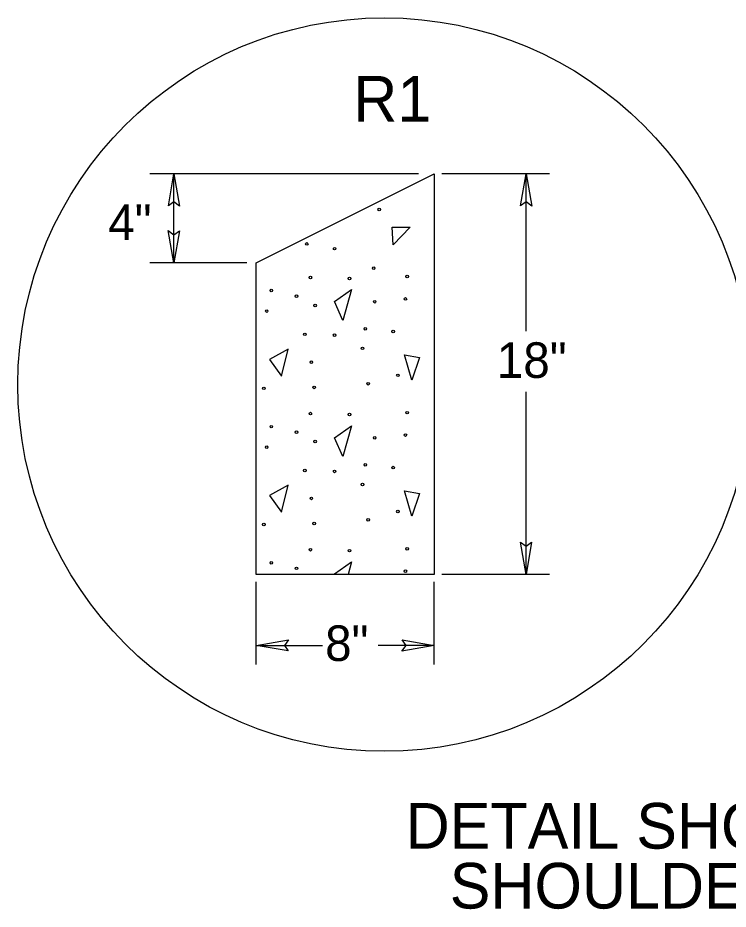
# Model space of a CAD drawing. Extents: x 1542177 to 1542464, y 45134 to 45344.
# Drawn here: x 1542311.98 to 1542327.96, y 45285.53 to 45305.56 of the extents above; entities that cross this region are included whole.
import ezdxf

# ---------------------------------------------------------------- set-up
doc = ezdxf.new("R2010")
doc.units = 0
for name, color, linetype in [('Default', 7, 'Continuous'), ('Typical Curb CELL', 7, 'Continuous'), ('Typical ID Circle CELL', 7, 'Continuous')]:
    doc.layers.add(name, color=color, linetype=linetype)

msp = doc.modelspace()

# ---------------------------------------------------------------- linework, layer by layer
at = {"layer": 'Default'}
for p, q in [((1542320.995, 45302.053), (1542314.954, 45302.053)), ((1542315.495, 45300.053), (1542315.495, 45302.053)), ((1542323.939, 45302.053), (1542321.515, 45302.053)), ((1542323.412, 45298.52), (1542323.412, 45302.053)), ((1542317.135, 45300.053), (1542314.954, 45300.053)), ((1542323.412, 45293.053), (1542323.412, 45297.151)), ((1542323.939, 45293.053), (1542321.515, 45293.053)), ((1542317.345, 45291.024), (1542317.345, 45292.884)), ((1542321.345, 45291.024), (1542321.345, 45292.884)), ((1542317.345, 45291.456), (1542318.834, 45291.456)), ((1542321.345, 45291.456), (1542320.085, 45291.456))]:
    msp.add_line(p, q, dxfattribs=at)
for points in [[(1542315.371, 45301.333), (1542315.495, 45302.053), (1542315.623, 45301.329), (1542315.495, 45301.421)], [(1542323.288, 45301.333), (1542323.412, 45302.053), (1542323.54, 45301.329), (1542323.412, 45301.421)], [(1542315.619, 45300.773), (1542315.495, 45300.053), (1542315.367, 45300.777), (1542315.495, 45300.685)], [(1542323.536, 45293.773), (1542323.412, 45293.053), (1542323.284, 45293.777), (1542323.412, 45293.685)], [(1542318.065, 45291.332), (1542317.345, 45291.456), (1542318.069, 45291.584), (1542317.977, 45291.456)], [(1542320.625, 45291.58), (1542321.345, 45291.456), (1542320.621, 45291.328), (1542320.713, 45291.456)]]:
    msp.add_lwpolyline(points, close=True, dxfattribs=at)
at = {"layer": 'Typical Curb CELL'}
for p, q in [((1542317.345, 45300.053), (1542321.345, 45302.053)), ((1542321.345, 45302.053), (1542321.345, 45293.053)), ((1542320.404, 45300.854), (1542320.803, 45300.854)), ((1542320.427, 45300.455), (1542320.404, 45300.854)), ((1542320.803, 45300.854), (1542320.427, 45300.455)), ((1542317.345, 45293.053), (1542317.345, 45300.053)), ((1542319.107, 45299.181), (1542319.487, 45299.451)), ((1542319.487, 45299.451), (1542319.295, 45298.759)), ((1542319.295, 45298.759), (1542319.107, 45299.181)), ((1542318.061, 45298.112), (1542317.644, 45297.883)), ((1542317.914, 45297.507), (1542318.061, 45298.112)), ((1542320.679, 45297.988), (1542321.014, 45297.924)), ((1542320.844, 45297.42), (1542320.679, 45297.988)), ((1542321.014, 45297.924), (1542320.844, 45297.42)), ((1542317.644, 45297.883), (1542317.914, 45297.507)), ((1542319.107, 45296.122), (1542319.487, 45296.392)), ((1542319.487, 45296.392), (1542319.295, 45295.7)), ((1542319.295, 45295.7), (1542319.107, 45296.122)), ((1542318.061, 45295.054), (1542317.644, 45294.824)), ((1542317.914, 45294.448), (1542318.061, 45295.054)), ((1542320.679, 45294.93), (1542321.014, 45294.866)), ((1542320.844, 45294.361), (1542320.679, 45294.93)), ((1542317.644, 45294.824), (1542317.914, 45294.448)), ((1542321.014, 45294.866), (1542320.844, 45294.361)), ((1542319.107, 45293.063), (1542319.487, 45293.334)), ((1542319.487, 45293.334), (1542319.409, 45293.053)), ((1542321.345, 45293.053), (1542317.345, 45293.053)), ((1542319.111, 45293.053), (1542319.107, 45293.063))]:
    msp.add_line(p, q, dxfattribs=at)
for centre in [(1542320.112, 45301.251), (1542318.48, 45300.477), (1542319.107, 45300.372), (1542319.986, 45299.933), (1542318.563, 45299.724), (1542319.443, 45299.703), (1542320.74, 45299.745), (1542317.684, 45299.43), (1542318.249, 45299.305), (1542318.668, 45299.096), (1542320.008, 45299.179), (1542320.699, 45299.242), (1542317.58, 45298.97), (1542319.798, 45298.572), (1542320.426, 45298.51), (1542318.438, 45298.447), (1542319.107, 45298.426), (1542319.736, 45298.132), (1542318.584, 45297.819), (1542320.531, 45297.525), (1542319.861, 45297.337), (1542317.516, 45297.233), (1542318.647, 45297.254), (1542318.563, 45296.665), (1542319.443, 45296.644), (1542320.74, 45296.686), (1542317.684, 45296.372), (1542318.249, 45296.247), (1542320.008, 45296.121), (1542320.699, 45296.183), (1542317.58, 45295.911), (1542318.668, 45296.037), (1542319.798, 45295.514), (1542318.438, 45295.388), (1542319.107, 45295.367), (1542320.426, 45295.451), (1542319.736, 45295.074), (1542318.584, 45294.76), (1542320.531, 45294.467), (1542317.516, 45294.174), (1542318.647, 45294.195), (1542319.861, 45294.278), (1542318.563, 45293.607), (1542319.443, 45293.585), (1542320.74, 45293.627), (1542317.684, 45293.313), (1542318.249, 45293.188), (1542320.699, 45293.125)]:
    msp.add_circle(centre, 0.0294, dxfattribs=at)
at = {"layer": 'Typical ID Circle CELL'}
msp.add_circle((1542320.225, 45297.318), 8.241, dxfattribs=at)

# ---------------------------------------------------------------- texts
at = {"layer": 'Default'}
for s, height, p in [('R1', 1.0263, (1542319.526, 45303.226)), ('4"', 0.8, (1542314.017, 45300.565)), ('18"', 0.8, (1542322.755, 45297.467)), ('8"', 0.8, (1542318.894, 45291.106)), ('DETAIL SHOWING SPECIAL', 1.02627, (1542320.704, 45286.889)), ('SHOULDER BERM CURB', 1.02627, (1542321.695, 45285.543))]:
    msp.add_text(s, height=height, dxfattribs=at).set_placement(p)

doc.saveas('drawing.dxf')
